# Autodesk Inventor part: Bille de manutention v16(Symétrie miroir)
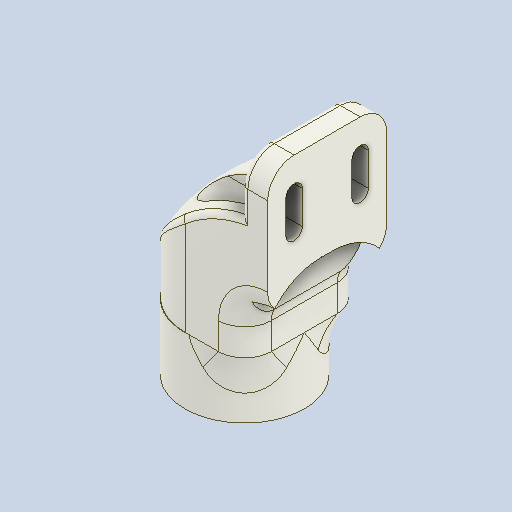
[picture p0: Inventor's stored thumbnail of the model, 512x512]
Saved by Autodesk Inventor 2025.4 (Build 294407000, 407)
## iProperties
Created: 2026-06
Part Number: Bille de manutention v16(Symétrie miroir)
Material: Generic
Document SubType Name: Modeling
Designer: AdminForWorker
Density: 1 g/cm^3
Appearance: Default
Title: Bille de manutention v16(Symétrie miroir)
Author: AdminForWorker
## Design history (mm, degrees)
feature "Body1"
feature "Body2"
body "Solid1"
body "Solid2"
